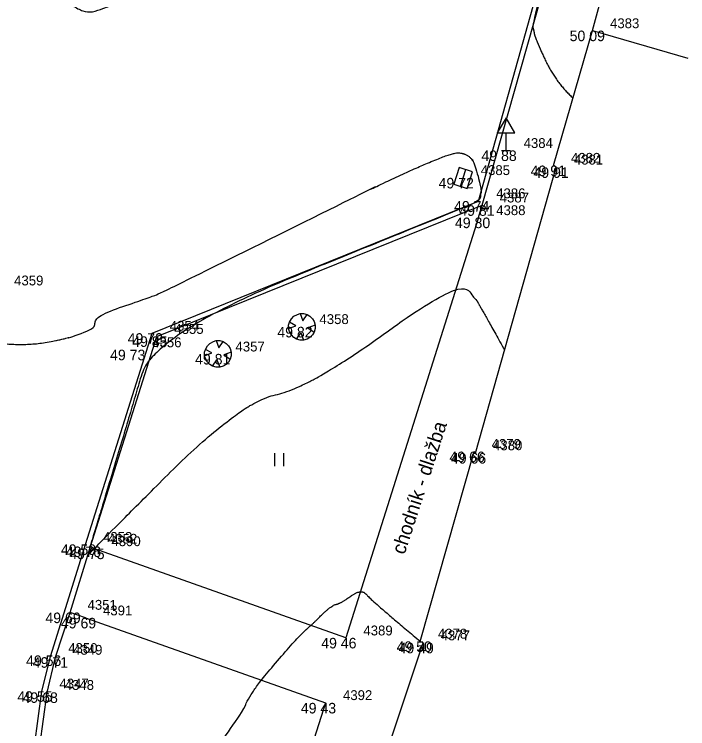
# Model space of a CAD drawing. Extents: x -704017 to -701500, y -1008977 to -1008450.
# Drawn here: x -701730.96 to -701711.79, y -1008947.47 to -1008927.14 of the extents above; entities that cross this region are included whole.
import ezdxf

# ---------------------------------------------------------------- set-up
doc = ezdxf.new("R2010")
doc.units = 0
for name, color, linetype in [('Z_body', 7, 'Continuous'), ('Z_body_cisla', 7, 'Continuous'), ('Z_body_vysky', 7, 'Continuous'), ('Z_budovy', 7, 'Continuous'), ('Z_chodnik', 7, 'Continuous'), ('Z_dopravni_znaceni', 7, 'Continuous'), ('Z_komunikace', 7, 'Continuous'), ('Z_obruby', 7, 'Continuous'), ('Z_popis', 7, 'Continuous'), ('Z_site_znaky_kanalizace', 7, 'Continuous'), ('Z_vrstevnice_hlavni', 7, 'Continuous'), ('Z_vrstevnice_vedlejsi', 7, 'Continuous'), ('Z_vstupy', 7, 'Continuous'), ('Z_zelen_jednotliva', 7, 'Continuous')]:
    doc.layers.add(name, color=color, linetype=linetype)

# ---------------------------------------------------------------- blocks, each defined once
blk = doc.blocks.new('POINT_DISPLAY')
blk.add_line((0, 0), (0, 0))
blk = doc.blocks.new('Z306')
for p, q in [((-0.13, 0.17), (-0.13, -0.2)), ((0.13, 0.17), (0.13, -0.2))]:
    blk.add_line(p, q)
blk = doc.blocks.new('Z23')
for p, q in [((-0.35, 0.13), (-0.3, 0.23)), ((-0.3, 0.23), (-0.23, 0.3)), ((-0.23, 0.3), (-0.13, 0.35)), ((-0.13, 0.35), (-0.05, 0.38)), ((-0.05, 0.38), (0.05, 0.38)), ((-0.05, 0.38), (0.03, 0.17)), ((0.03, 0.17), (0.15, 0.35)), ((0.05, 0.38), (0.15, 0.35)), ((0.15, 0.35), (0.23, 0.3)), ((0.23, 0.3), (0.3, 0.23)), ((0.3, 0.23), (0.35, 0.15)), ((-0.38, 0.05), (-0.35, 0.13)), ((-0.38, -0.05), (-0.38, 0.05)), ((-0.38, -0.05), (-0.17, 0.03)), ((-0.17, 0.03), (-0.35, 0.13)), ((0.38, 0.05), (0.17, -0.03)), ((0.35, 0.15), (0.38, 0.05)), ((0.38, 0.05), (0.38, -0.05)), ((-0.35, -0.13), (-0.38, -0.05)), ((-0.3, -0.23), (-0.35, -0.13)), ((-0.15, -0.35), (-0.03, -0.17)), ((-0.03, -0.17), (0.05, -0.38)), ((0.17, -0.03), (0.35, -0.15)), ((0.35, -0.15), (0.3, -0.23)), ((0.38, -0.05), (0.35, -0.15)), ((-0.23, -0.3), (-0.3, -0.23)), ((-0.15, -0.35), (-0.23, -0.3)), ((-0.05, -0.38), (-0.15, -0.35)), ((0.05, -0.38), (-0.05, -0.38)), ((0.15, -0.35), (0.05, -0.38)), ((0.23, -0.3), (0.15, -0.35)), ((0.3, -0.23), (0.23, -0.3))]:
    blk.add_line(p, q)
blk = doc.blocks.new('Z527')
for p, q in [((0, 0.93), (-0.25, 0.5)), ((0.25, 0.5), (0, 0.93)), ((-0.25, 0.5), (0.25, 0.5)), ((0, 0), (0, 0.5)), ((-0.13, 0), (0.13, 0))]:
    blk.add_line(p, q)
blk = doc.blocks.new('Z38')
for p, q in [((0.25, 0.2), (-0.25, 0.2)), ((-0.25, 0.2), (-0.25, -0.2)), ((-0.25, 0), (0.25, 0)), ((0.25, -0.2), (0.25, 0.2)), ((-0.25, -0.2), (0.25, -0.2))]:
    blk.add_line(p, q)

msp = doc.modelspace()

# ---------------------------------------------------------------- linework, layer by layer
at = {"layer": 'Z_budovy'}
for p, q in [((-701715.61, -1008931.44), (-701714.5, -1008927.6)), ((-701714.5, -1008927.6), (-701711.79, -1008928.38)), ((-701717.83, -1008939.62), (-701715.53, -1008931.49)), ((-701715.53, -1008931.49), (-701715.61, -1008931.44)), ((-701719.4, -1008944.98), (-701717.87, -1008939.58)), ((-701717.87, -1008939.58), (-701717.83, -1008939.62)), ((-701721.5, -1008951.56), (-701719.32, -1008945.02)), ((-701719.32, -1008945.02), (-701719.4, -1008944.98))]:
    msp.add_line(p, q, dxfattribs=at)
at = {"layer": 'Z_chodnik'}
for p, q in [((-701717.74, -1008932.92), (-701717.64, -1008932.57)), ((-701717.74, -1008932.92), (-701721.52, -1008944.88)), ((-701728.69, -1008942.34), (-701728.79, -1008942.28)), ((-701721.52, -1008944.88), (-701728.69, -1008942.34)), ((-701728.93, -1008944.31), (-701729.37, -1008944.16)), ((-701728.93, -1008944.31), (-701722.1, -1008946.73)), ((-701722.1, -1008946.73), (-701726.34, -1008959.95))]:
    msp.add_line(p, q, dxfattribs=at)
at = {"layer": 'Z_komunikace'}
for p, q in [((-701717.74, -1008932.45), (-701716.12, -1008926.66)), ((-701727.03, -1008936.21), (-701717.74, -1008932.45)), ((-701728.93, -1008942.22), (-701727.03, -1008936.21)), ((-701729.92, -1008945.38), (-701728.93, -1008942.22)), ((-701730.17, -1008946.4), (-701729.92, -1008945.38)), ((-701730.44, -1008948.38), (-701730.17, -1008946.4))]:
    msp.add_line(p, q, dxfattribs=at)
at = {"layer": 'Z_obruby'}
for p, q in [((-701717.64, -1008932.57), (-701715.98, -1008926.7)), ((-701726.9, -1008936.3), (-701717.64, -1008932.57)), ((-701728.79, -1008942.28), (-701726.9, -1008936.3)), ((-701729.37, -1008944.16), (-701728.79, -1008942.28)), ((-701729.78, -1008945.43), (-701729.37, -1008944.16)), ((-701730.02, -1008946.43), (-701729.78, -1008945.43)), ((-701730.29, -1008948.39), (-701730.02, -1008946.43))]:
    msp.add_line(p, q, dxfattribs=at)
at = {"layer": 'Z_vrstevnice_hlavni'}
msp.add_open_spline([(-701734.748, -1008919.221), (-701734.673, -1008919.238), (-701734.423, -1008919.246), (-701734.173, -1008919.026), (-701733.784, -1008918.688), (-701732.337, -1008917.695), (-701732.568, -1008918.47), (-701733.6, -1008921.842), (-701734.4, -1008924.391), (-701734.431, -1008925.289), (-701734.463, -1008927.053), (-701733.955, -1008925.613), (-701732.74, -1008922.15), (-701730.709, -1008924.804), (-701729.26, -1008927.251), (-701727.968, -1008926.819), (-701723.48, -1008925.02), (-701715.766, -1008925.426), (-701715.805, -1008925.754), (-701715.97, -1008926.696), (-701716.027, -1008926.687), (-701716.162, -1008927.295), (-701716.206, -1008927.5), (-701716.176, -1008927.562), (-701716.143, -1008927.793), (-701715.554, -1008929.061), (-701715.055, -1008929.52)], degree=2, dxfattribs=at)
at = {"layer": 'Z_vrstevnice_vedlejsi'}
for points in [[(-701739.271, -1008933.2), (-701738.296, -1008932.621), (-701738.085, -1008932.475), (-701737.515, -1008930.75), (-701735.646, -1008927.852), (-701736.176, -1008929.68), (-701737.366, -1008933.468), (-701737.397, -1008934.375), (-701737.905, -1008937.895), (-701736.288, -1008933.173), (-701736.004, -1008932.369), (-701735.874, -1008931.998), (-701735.778, -1008931.97), (-701734.454, -1008933.833), (-701733.419, -1008936.135), (-701732.86, -1008936.12), (-701730.858, -1008936.658), (-701728.653, -1008936.177), (-701728.691, -1008935.726), (-701727.131, -1008935.204), (-701726.65, -1008935.011), (-701718.748, -1008931.065), (-701717.899, -1008931.09), (-701717.659, -1008932.161), (-701717.679, -1008932.252), (-701717.726, -1008932.467), (-701718.573, -1008932.8), (-701727, -1008936.231), (-701727.681, -1008938.577), (-701728.798, -1008942.276), (-701728.873, -1008942.549), (-701728.69, -1008942.34), (-701724.536, -1008938.185), (-701722.527, -1008937.751), (-701718.296, -1008934.679), (-701717.786, -1008935.299), (-701717.772, -1008935.313), (-701717.002, -1008936.693)], [(-701773.971, -1008959.221), (-701773.611, -1008958.899), (-701768.633, -1008950.858), (-701768.32, -1008950.374), (-701768.26, -1008950.536), (-701767.757, -1008950.395), (-701767.625, -1008950.96), (-701767.096, -1008950.484), (-701765.713, -1008950.612), (-701763.054, -1008947.869), (-701762.897, -1008947.613), (-701762.622, -1008947.644), (-701762.63, -1008947.61), (-701762.506, -1008947.635), (-701760.8, -1008947.99), (-701759.208, -1008948.143), (-701758.947, -1008948.041), (-701758.388, -1008948.143), (-701758.235, -1008948.241), (-701751.691, -1008949.254), (-701747.637, -1008948.233), (-701746.394, -1008948.75), (-701743.001, -1008950.306), (-701742.288, -1008950.624), (-701736.747, -1008953.52), (-701735.858, -1008954.034), (-701735.46, -1008954.08), (-701735.395, -1008953.825), (-701735.333, -1008953.766), (-701735.151, -1008953.611), (-701734.606, -1008953.07), (-701731.409, -1008949.369), (-701730.446, -1008948.79), (-701730.434, -1008950.022), (-701730.433, -1008950.432), (-701730.287, -1008951.52), (-701730.154, -1008952.408), (-701730.018, -1008952.903), (-701729.76, -1008953.885), (-701728.989, -1008953.081), (-701728.637, -1008952.767), (-701728.025, -1008951.97), (-701727.684, -1008951.31), (-701724.593, -1008947.235), (-701724.318, -1008946.646), (-701723.939, -1008946.078), (-701722.809, -1008944.781), (-701722.509, -1008944.53), (-701721.936, -1008943.957), (-701721.659, -1008943.897), (-701721.075, -1008943.473), (-701720.79, -1008943.82), (-701719.4, -1008944.98)]]:
    msp.add_open_spline(points, degree=2, dxfattribs=at)
at = {"layer": 'Z_vstupy'}
msp.add_line((-701714.5, -1008927.6), (-701713.26, -1008923.06), dxfattribs=at)

# ---------------------------------------------------------------- block references
at = {"layer": 'Z_body'}
for p in [(-701714.5, -1008927.6), (-701716.96, -1008931.01), (-701715.61, -1008931.44), (-701715.53, -1008931.49), (-701718.18, -1008931.79), (-701717.74, -1008932.45), (-701717.64, -1008932.57), (-701717.74, -1008932.92), (-701727.03, -1008936.21), (-701722.77, -1008936.03), (-701726.9, -1008936.3), (-701727.53, -1008936.68), (-701725.16, -1008936.8), (-701717.87, -1008939.58), (-701717.83, -1008939.62), (-701728.93, -1008942.22), (-701728.79, -1008942.28), (-701728.69, -1008942.34), (-701729.37, -1008944.16), (-701728.93, -1008944.31), (-701721.52, -1008944.88), (-701719.4, -1008944.98), (-701719.32, -1008945.02), (-701729.92, -1008945.38), (-701729.78, -1008945.43), (-701730.17, -1008946.4), (-701730.02, -1008946.43), (-701722.1, -1008946.73)]:
    msp.add_blockref('POINT_DISPLAY', p, dxfattribs=at)
at = {"layer": 'Z_dopravni_znaceni'}
msp.add_blockref('Z527', (-701716.96, -1008931.01), dxfattribs=at)
at = {"layer": 'Z_popis'}
msp.add_blockref('Z306', (-701723.42, -1008939.79), dxfattribs=at)
at = {"layer": 'Z_site_znaky_kanalizace', "rotation": 72}
msp.add_blockref('Z38', (-701718.18, -1008931.79), dxfattribs=at)
at = {"layer": 'Z_zelen_jednotliva'}
for p in [(-701722.77, -1008936.03), (-701725.16, -1008936.8)]:
    msp.add_blockref('Z23', p, dxfattribs=at)

# ---------------------------------------------------------------- texts
at = {"layer": 'Z_body_cisla'}
for s, p in [('4383', (-701714, -1008927.53)), ('4384', (-701716.46, -1008930.94)), ('4382', (-701715.11, -1008931.36)), ('4381', (-701715.03, -1008931.41)), ('4385', (-701717.68, -1008931.71)), ('4386', (-701717.24, -1008932.37)), ('4387', (-701717.14, -1008932.49)), ('4388', (-701717.24, -1008932.85)), ('4359', (-701730.96, -1008934.85)), ('4358', (-701722.27, -1008935.95)), ('4354', (-701726.53, -1008936.14)), ('4355', (-701726.4, -1008936.23)), ('4356', (-701727.03, -1008936.61)), ('4357', (-701724.66, -1008936.73)), ('4379', (-701717.37, -1008939.5)), ('4380', (-701717.33, -1008939.54)), ('4353', (-701728.43, -1008942.15)), ('4352', (-701728.29, -1008942.2)), ('4390', (-701728.19, -1008942.27)), ('4351', (-701728.87, -1008944.08)), ('4391', (-701728.43, -1008944.24)), ('4389', (-701721.02, -1008944.81)), ('4378', (-701718.9, -1008944.9)), ('4377', (-701718.82, -1008944.95)), ('4350', (-701729.42, -1008945.31)), ('4349', (-701729.28, -1008945.36)), ('4347', (-701729.67, -1008946.32)), ('4348', (-701729.52, -1008946.36)), ('4392', (-701721.6, -1008946.65))]:
    msp.add_text(s, height=0.28, dxfattribs=at).set_placement(p)
at = {"layer": 'Z_body_vysky'}
for s, p in [('50 09', (-701715.15, -1008927.9)), ('49 88', (-701717.66, -1008931.31)), ('49 91', (-701716.26, -1008931.74)), ('49 91', (-701716.18, -1008931.79)), ('49 72', (-701718.88, -1008932.09)), ('49 74', (-701718.44, -1008932.75)), ('49 81', (-701718.29, -1008932.87)), ('49 80', (-701718.415, -1008933.22)), ('49 72', (-701727.73, -1008936.51)), ('49 82', (-701723.47, -1008936.33)), ('49 85', (-701727.6, -1008936.6)), ('49 73', (-701728.23, -1008936.98)), ('49 81', (-701725.81, -1008937.1)), ('49 66', (-701718.57, -1008939.88)), ('49 66', (-701718.53, -1008939.92)), ('49 59', (-701729.63, -1008942.52)), ('49 76', (-701729.49, -1008942.58)), ('49 75', (-701729.39, -1008942.64)), ('49 69', (-701730.07, -1008944.46)), ('49 69', (-701729.63, -1008944.61)), ('49 46', (-701722.22, -1008945.18)), ('49 50', (-701720.075, -1008945.28)), ('49 49', (-701720.02, -1008945.32)), ('49 56', (-701730.62, -1008945.68)), ('49 71', (-701730.43, -1008945.73)), ('49 55', (-701730.87, -1008946.7)), ('49 68', (-701730.72, -1008946.73)), ('49 43', (-701722.8, -1008947.03))]:
    msp.add_text(s, height=0.3, dxfattribs=at).set_placement(p)
at = {"layer": 'Z_popis'}
msp.add_text('chodník - dlažba', height=0.4, rotation=72, dxfattribs=at).set_placement((-701719.85, -1008942.53))

doc.saveas('drawing.dxf')
